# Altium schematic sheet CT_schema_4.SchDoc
size 245 x 200 mm
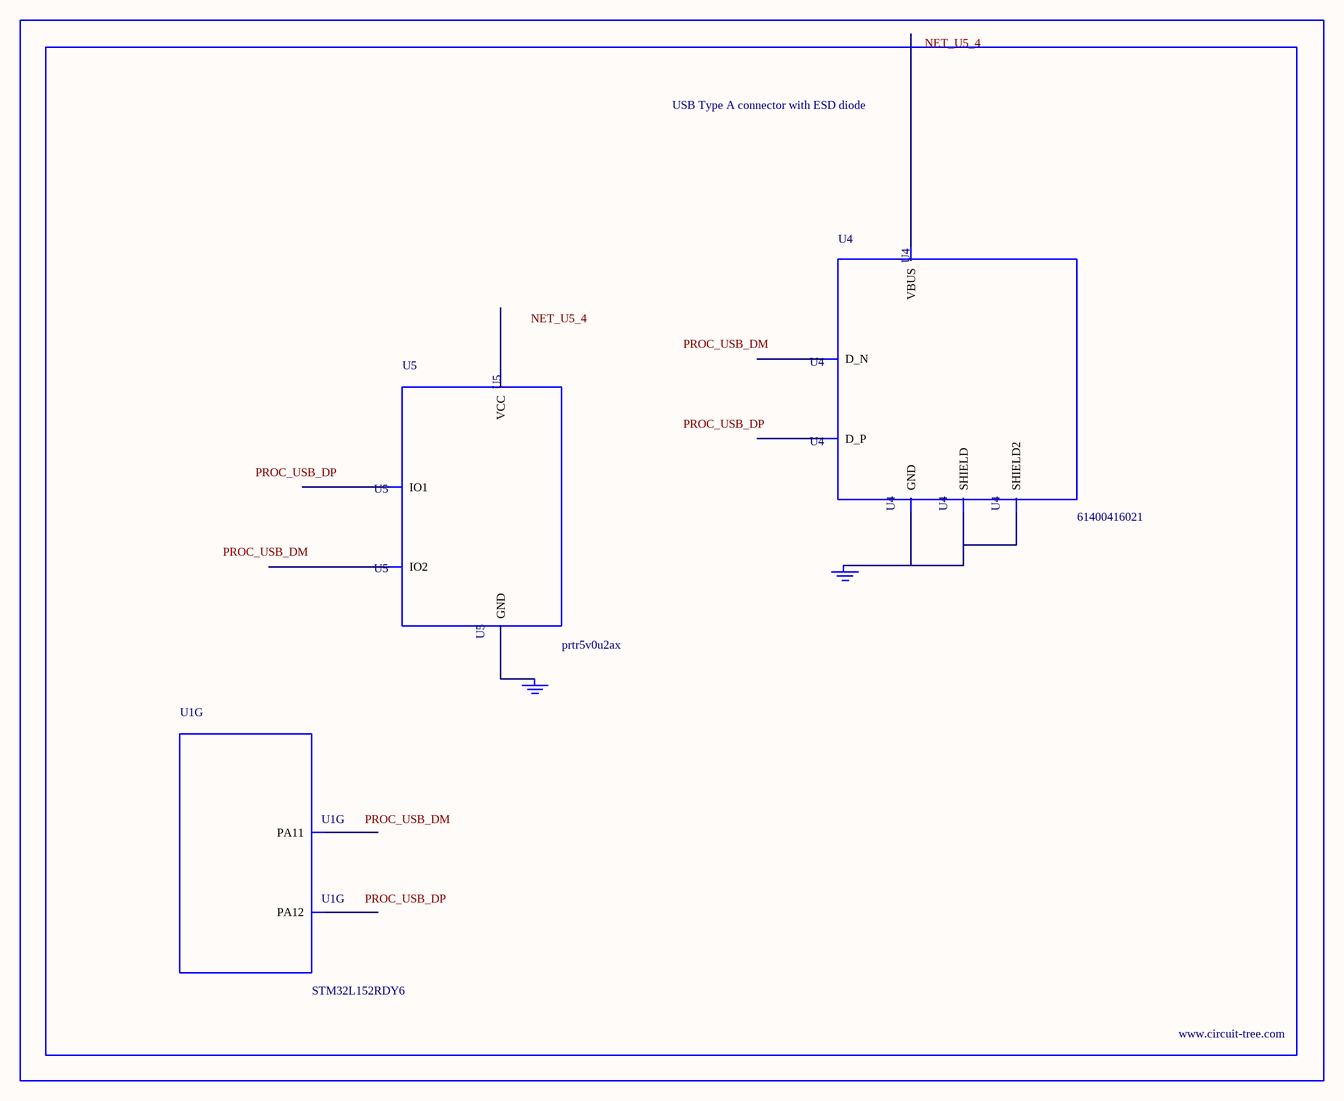
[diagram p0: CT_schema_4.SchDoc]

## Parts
BORDER3  (no value)
GND_INSTANCE_3_0  (no value)
GND_INSTANCE_3_1  (no value)
U1  STM32L152RDY6  [WLCSP64]  (part G of 7)
U4  61400416021  [USB-A-H]
U5  prtr5v0u2ax  [SOT143B]

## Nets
NetGND_INSTANCE_3_0_0: GND_INSTANCE_3_0.0(GND) U4.4(GND) U4.5(SHIELD) U4.6(SHIELD2)
NetGND_INSTANCE_3_1_0: GND_INSTANCE_3_1.0(GND) U5.1(GND)

Not connected (* = marked no-connect by the designer): U1 C1(PA11) C2(PA12); U4 1(VBUS) 2(D_N) 3(D_P); U5 2(IO1) 3(IO2) 4(VCC)

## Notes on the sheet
- Labels drawn without touching a wire or pin: NET_U5_4, PROC_USB_DM, PROC_USB_DP

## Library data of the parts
BORDER3 = BORDER_PAGE3
GND_INSTANCE_3_0 GND_INSTANCE_3_1 = GND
